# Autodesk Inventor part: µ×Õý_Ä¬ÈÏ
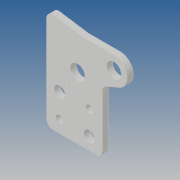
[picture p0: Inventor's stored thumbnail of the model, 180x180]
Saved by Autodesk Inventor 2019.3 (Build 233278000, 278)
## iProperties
Created: 2012-10
Part Number: µ×Õý_Ä¬ÈÏ
Material: Ogólny
Document SubType Name: Modeling
Designer: CADENGINEERING4
Density: 1 g/cm^3
Appearance: Domyślna
Author: CADENGINEERING4
Revision Number: ÈÎºÎ
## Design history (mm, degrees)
feature "NONE"
node "Bryła1"
